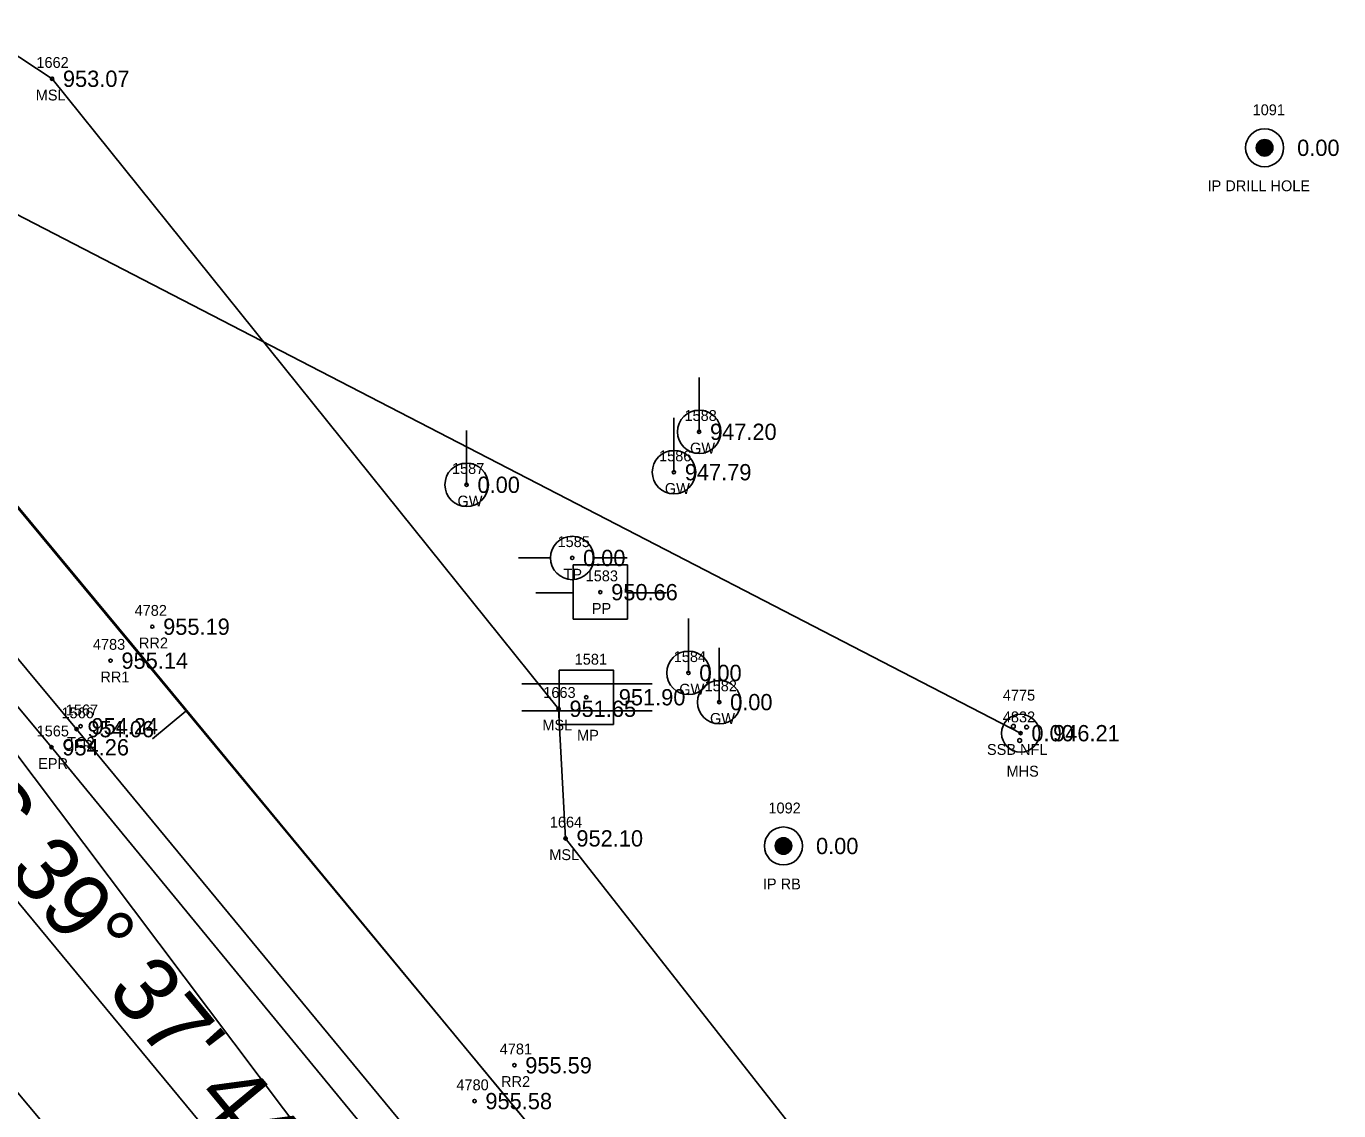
# Model space of a CAD drawing. Extents: x 1575382 to 1578175, y 1099175 to 1101955.
# Drawn here: x 1576480.6 to 1576601.4, y 1099501.7 to 1099601.6 of the extents above; entities that cross this region are included whole.
import ezdxf

# ---------------------------------------------------------------- set-up
doc = ezdxf.new("R2010")
doc.units = 0
for name, color, linetype in [('RD_EX_Conc', 7, 'Continuous'), ('RD_EX_Conc_txCode', 7, 'Continuous'), ('RD_EX_DR_Inlet', 7, 'Continuous'), ('RD_EX_DV_Prop_txCode', 7, 'Continuous'), ('RD_EX_DV_PropPin', 7, 'Continuous'), ('RD_EX_Misc', 7, 'Continuous'), ('RD_EX_Misc_txCode', 7, 'Continuous'), ('RD_EX_RailRoad', 7, 'Continuous'), ('RD_EX_RailRoad_txCode', 7, 'Continuous'), ('RD_EX_Road', 7, 'Continuous'), ('RD_EX_Road_txCode', 7, 'Continuous'), ('RD_EX_TX_Conc_ELEV', 7, 'Continuous'), ('RD_EX_TX_DV_Prop_ELEV', 7, 'Continuous'), ('RD_EX_TX_Misc_ELEV', 7, 'Continuous'), ('RD_EX_TX_RailRoad_ELEV', 7, 'Continuous'), ('RD_EX_TX_Road_ELEV', 7, 'Continuous'), ('RD_EX_TX_UT_ELEV', 7, 'Continuous'), ('RD_EX_UT', 7, 'Continuous'), ('RD_EX_UT_txCode', 7, 'Continuous'), ('RD_HC_Cl', 7, 'Continuous'), ('RD_HC_Data', 7, 'Continuous'), ('RD_HC_Data_Tic', 7, 'Continuous'), ('RD_HC_Survey_ELEV', 7, 'Continuous'), ('RD_SMD_Locator', 7, 'Continuous')]:
    doc.layers.add(name, color=color, linetype=linetype)

msp = doc.modelspace()

# ---------------------------------------------------------------- linework, layer by layer
at = {"layer": 'RD_EX_Conc'}
msp.add_lwpolyline([(1576448.28, 1099581.24), (1576485.22, 1099536.89), (1576516.55, 1099498.95), (1576548.71, 1099459.94), (1576580.64, 1099421.45)], dxfattribs=at)
at = {"layer": 'RD_EX_DR_Inlet'}
for centre, radius in [((1576572.13, 1099536.52), 1.75), ((1576571.47, 1099537.15), 0.175), ((1576572.69, 1099537.08), 0.175), ((1576572.05, 1099535.85), 0.175)]:
    msp.add_circle(centre, radius, dxfattribs=at)
at = {"layer": 'RD_EX_DV_PropPin'}
for p, q in [((1576593.87, 1099590.24), (1576593.87, 1099590.64)), ((1576593.9, 1099590.14), (1576593.9, 1099590.74)), ((1576593.94, 1099590.07), (1576593.94, 1099590.81)), ((1576593.97, 1099590.01), (1576593.97, 1099590.87)), ((1576594.01, 1099589.97), (1576594.01, 1099590.91)), ((1576594.04, 1099589.92), (1576594.04, 1099590.95)), ((1576594.08, 1099589.89), (1576594.08, 1099590.99)), ((1576594.11, 1099589.86), (1576594.11, 1099591.02)), ((1576594.15, 1099589.83), (1576594.15, 1099591.05)), ((1576594.18, 1099589.8), (1576594.18, 1099591.07)), ((1576594.22, 1099589.78), (1576594.22, 1099591.1)), ((1576594.25, 1099589.76), (1576594.25, 1099591.11)), ((1576594.29, 1099589.75), (1576594.29, 1099591.13)), ((1576594.32, 1099589.73), (1576594.32, 1099591.15)), ((1576594.36, 1099589.72), (1576594.36, 1099591.16)), ((1576594.39, 1099589.71), (1576594.39, 1099591.17)), ((1576594.43, 1099589.7), (1576594.43, 1099591.18)), ((1576594.46, 1099589.69), (1576594.46, 1099591.19)), ((1576594.5, 1099589.69), (1576594.5, 1099591.19)), ((1576594.53, 1099589.68), (1576594.53, 1099591.2)), ((1576594.57, 1099589.68), (1576594.57, 1099591.2)), ((1576594.6, 1099589.68), (1576594.6, 1099591.2)), ((1576594.64, 1099589.68), (1576594.64, 1099591.2)), ((1576594.67, 1099589.68), (1576594.67, 1099591.2)), ((1576594.71, 1099589.69), (1576594.71, 1099591.19)), ((1576594.74, 1099589.69), (1576594.74, 1099591.19)), ((1576594.78, 1099589.7), (1576594.78, 1099591.18)), ((1576594.81, 1099589.71), (1576594.81, 1099591.17)), ((1576594.85, 1099589.72), (1576594.85, 1099591.16)), ((1576594.88, 1099589.73), (1576594.88, 1099591.15)), ((1576594.92, 1099589.75), (1576594.92, 1099591.13)), ((1576594.95, 1099589.76), (1576594.95, 1099591.11)), ((1576594.99, 1099589.78), (1576594.99, 1099591.1)), ((1576595.02, 1099589.8), (1576595.02, 1099591.07)), ((1576595.06, 1099589.83), (1576595.06, 1099591.05)), ((1576595.09, 1099589.86), (1576595.09, 1099591.02)), ((1576595.13, 1099589.89), (1576595.13, 1099590.99)), ((1576595.16, 1099589.92), (1576595.16, 1099590.95)), ((1576595.2, 1099589.97), (1576595.2, 1099590.91)), ((1576595.23, 1099590.01), (1576595.23, 1099590.87)), ((1576595.27, 1099590.07), (1576595.27, 1099590.81)), ((1576595.3, 1099590.14), (1576595.3, 1099590.74)), ((1576595.34, 1099590.24), (1576595.34, 1099590.64)), ((1576549.57, 1099525.93), (1576549.57, 1099526.33)), ((1576549.6, 1099525.83), (1576549.6, 1099526.43)), ((1576549.64, 1099525.76), (1576549.64, 1099526.5)), ((1576549.67, 1099525.7), (1576549.67, 1099526.56)), ((1576549.71, 1099525.66), (1576549.71, 1099526.6)), ((1576549.74, 1099525.62), (1576549.74, 1099526.65)), ((1576549.78, 1099525.58), (1576549.78, 1099526.68)), ((1576549.81, 1099525.55), (1576549.81, 1099526.71)), ((1576549.85, 1099525.52), (1576549.85, 1099526.74)), ((1576549.88, 1099525.5), (1576549.88, 1099526.77)), ((1576549.92, 1099525.47), (1576549.92, 1099526.79)), ((1576549.95, 1099525.45), (1576549.95, 1099526.81)), ((1576549.99, 1099525.44), (1576549.99, 1099526.82)), ((1576550.02, 1099525.42), (1576550.02, 1099526.84)), ((1576550.06, 1099525.41), (1576550.06, 1099526.85)), ((1576550.09, 1099525.4), (1576550.09, 1099526.86)), ((1576550.13, 1099525.39), (1576550.13, 1099526.87)), ((1576550.16, 1099525.38), (1576550.16, 1099526.88)), ((1576550.2, 1099525.38), (1576550.2, 1099526.88)), ((1576550.23, 1099525.37), (1576550.23, 1099526.89)), ((1576550.27, 1099525.37), (1576550.27, 1099526.89)), ((1576550.3, 1099525.37), (1576550.3, 1099526.89)), ((1576550.34, 1099525.37), (1576550.34, 1099526.89)), ((1576550.37, 1099525.37), (1576550.37, 1099526.89)), ((1576550.41, 1099525.38), (1576550.41, 1099526.88)), ((1576550.44, 1099525.38), (1576550.44, 1099526.88)), ((1576550.48, 1099525.39), (1576550.48, 1099526.87)), ((1576550.51, 1099525.4), (1576550.51, 1099526.86)), ((1576550.55, 1099525.41), (1576550.55, 1099526.85)), ((1576550.58, 1099525.42), (1576550.58, 1099526.84)), ((1576550.62, 1099525.44), (1576550.62, 1099526.82)), ((1576550.65, 1099525.45), (1576550.65, 1099526.81)), ((1576550.69, 1099525.47), (1576550.69, 1099526.79)), ((1576550.72, 1099525.5), (1576550.72, 1099526.77)), ((1576550.76, 1099525.52), (1576550.76, 1099526.74)), ((1576550.79, 1099525.55), (1576550.79, 1099526.71)), ((1576550.83, 1099525.58), (1576550.83, 1099526.68)), ((1576550.86, 1099525.62), (1576550.86, 1099526.65)), ((1576550.9, 1099525.66), (1576550.9, 1099526.6)), ((1576550.93, 1099525.7), (1576550.93, 1099526.56)), ((1576550.97, 1099525.76), (1576550.97, 1099526.5)), ((1576551, 1099525.83), (1576551, 1099526.43)), ((1576551.04, 1099525.93), (1576551.04, 1099526.33))]:
    msp.add_line(p, q, dxfattribs=at)
for centre, radius in [((1576594.6, 1099590.44), 1.75), ((1576594.6, 1099590.44), 0.761), ((1576550.3, 1099526.13), 1.75), ((1576550.3, 1099526.13), 0.761)]:
    msp.add_circle(centre, radius, dxfattribs=at)
at = {"layer": 'RD_EX_Misc'}
msp.add_lwpolyline([(1576459.31, 1099612.41), (1576482.96, 1099596.8), (1576529.6, 1099538.77), (1576530.24, 1099526.83), (1576601.16, 1099436.41)], dxfattribs=at)
at = {"layer": 'RD_EX_RailRoad'}
msp.add_lwpolyline([(1576586.78, 1099428.1), (1576554.9, 1099466.71), (1576523.69, 1099504.28), (1576490.27, 1099544.77), (1576459.31, 1099582.09), (1576445.84, 1099598.34), (1576409.99, 1099641.44), (1576367.44, 1099692.66), (1576334.67, 1099732.08), (1576298.68, 1099775.46), (1576256.76, 1099825.95)], dxfattribs=at)
at = {"layer": 'RD_EX_Road'}
for points in [[(1576443.75, 1099596.96), (1576443.04, 1099588.29), (1576448.28, 1099581.24), (1576446.02, 1099579.49), (1576482.91, 1099535.22), (1576514.34, 1099496.99), (1576546.16, 1099458.39), (1576578.5, 1099419.58)], [(1576365.09, 1099547.1), (1576400.46, 1099578.87), (1576404.99, 1099582.28), (1576408.27, 1099583.27), (1576411.47, 1099582.29), (1576413.12, 1099580.85), (1576414.82, 1099582.11), (1576433.7, 1099559), (1576464.95, 1099521.11), (1576497.8, 1099481.91), (1576528.73, 1099444.46), (1576560.01, 1099406.61)]]:
    msp.add_lwpolyline(points, dxfattribs=at)
at = {"layer": 'RD_EX_UT'}
for p, q in [((1576542.54, 1099564.28), (1576542.54, 1099569.28)), ((1576540.22, 1099560.56), (1576540.22, 1099565.56)), ((1576521.13, 1099559.4), (1576521.13, 1099564.4)), ((1576525.92, 1099552.67), (1576528.85, 1099552.67)), ((1576535.93, 1099552.02), (1576530.93, 1099552.02)), ((1576530.93, 1099552.02), (1576530.93, 1099547.02)), ((1576532.85, 1099552.67), (1576535.92, 1099552.67)), ((1576535.93, 1099547.02), (1576535.93, 1099552.02)), ((1576527.5, 1099549.46), (1576530.97, 1099549.46)), ((1576535.86, 1099549.46), (1576539.5, 1099549.46)), ((1576530.93, 1099547.02), (1576535.93, 1099547.02)), ((1576541.55, 1099542.07), (1576541.55, 1099547.07)), ((1576544.39, 1099539.38), (1576544.39, 1099544.38)), ((1576526.21, 1099541.08), (1576538.21, 1099541.08)), ((1576526.21, 1099538.58), (1576538.21, 1099538.58))]:
    msp.add_line(p, q, dxfattribs=at)
for points in [[(1576131.49, 1099798.74), (1576305.27, 1099688.09), (1576417.78, 1099616.34), (1576572.13, 1099536.52)], [(1576589.46, 1099388.65), (1576430.6, 1099599.81), (1576417.78, 1099616.34)]]:
    msp.add_lwpolyline(points, dxfattribs=at)
msp.add_lwpolyline([(1576529.64, 1099542.33), (1576534.64, 1099542.33), (1576534.64, 1099537.33), (1576529.64, 1099537.33)], close=True, dxfattribs=at)
for centre in [(1576542.54, 1099564.28), (1576521.13, 1099559.4), (1576540.22, 1099560.56), (1576530.85, 1099552.66), (1576541.55, 1099542.07), (1576544.39, 1099539.38)]:
    msp.add_circle(centre, 2, dxfattribs=at)
at = {"layer": 'RD_HC_Cl'}
for p, q in [((1576594.9, 1099418.51), (1576256.8, 1099825.98)), ((1576414.59, 1099599.72), (1576569.26, 1099412.94))]:
    msp.add_line(p, q, dxfattribs=at)
at = {"layer": 'RD_HC_Data_Tic'}
msp.add_line((1576495.28, 1099538.56), (1576492.21, 1099536.01), dxfattribs=at)
at = {"layer": 'RD_SMD_Locator'}
for centre, radius in [((1576482.96, 1099596.8), 0.15), ((1576594.6, 1099590.44), 0.15), ((1576542.54, 1099564.28), 0.15), ((1576540.22, 1099560.56), 0.15), ((1576521.13, 1099559.4), 0.15), ((1576530.85, 1099552.66), 0.15), ((1576533.44, 1099549.51), 0.15), ((1576492.19, 1099546.33), 0.15), ((1576488.35, 1099543.2), 0.15), ((1576541.55, 1099542.07), 0.15), ((1576532.14, 1099539.83), 0.15), ((1576529.6, 1099538.77), 0.15), ((1576544.39, 1099539.38), 0.15), ((1576485.59, 1099537.16), 0.15), ((1576485.22, 1099536.89), 0.15), ((1576572.13, 1099536.52), 0.15), ((1576572.13, 1099536.52), 0.001), ((1576482.91, 1099535.22), 0.15), ((1576530.24, 1099526.83), 0.15), ((1576550.3, 1099526.13), 0.15), ((1576525.53, 1099505.93), 0.15), ((1576521.86, 1099502.63), 0.15)]:
    msp.add_circle(centre, radius, dxfattribs=at)

# ---------------------------------------------------------------- texts
at = {"layer": 'RD_EX_Conc_txCode'}
for s, p in [('1566', (1576483.83, 1099537.89)), ('1567', (1576484.22, 1099538.16)), ('TC2', (1576484.35, 1099535.16)), ('CFR', (1576483.99, 1099534.89))]:
    msp.add_text(s, height=1, dxfattribs=at).set_placement(p)
at = {"layer": 'RD_EX_DV_Prop_txCode'}
for s, p in [('1091', (1576593.5, 1099593.44)), ('IP DRILL HOLE', (1576589.35, 1099586.44)), ('1092', (1576548.92, 1099529.13)), ('IP RB', (1576548.41, 1099522.13))]:
    msp.add_text(s, height=1, dxfattribs=at).set_placement(p)
at = {"layer": 'RD_EX_Misc_txCode'}
for s, p in [('1662', (1576481.52, 1099597.8)), ('MSL', (1576481.46, 1099594.8)), ('1663', (1576528.19, 1099539.77)), ('MSL', (1576528.1, 1099536.77)), ('1664', (1576528.79, 1099527.83)), ('MSL', (1576528.74, 1099524.83))]:
    msp.add_text(s, height=1, dxfattribs=at).set_placement(p)
at = {"layer": 'RD_EX_RailRoad_txCode'}
for s, p in [('4782', (1576490.56, 1099547.33)), ('4783', (1576486.72, 1099544.2)), ('RR2', (1576490.96, 1099544.33)), ('RR1', (1576487.41, 1099541.2)), ('4781', (1576524.18, 1099506.93)), ('4780', (1576520.19, 1099503.63)), ('RR2', (1576524.3, 1099503.93))]:
    msp.add_text(s, height=1, dxfattribs=at).set_placement(p)
at = {"layer": 'RD_EX_Road_txCode'}
for s, p in [('1565', (1576481.54, 1099536.22)), ('EPR', (1576481.68, 1099533.22))]:
    msp.add_text(s, height=1, dxfattribs=at).set_placement(p)
at = {"layer": 'RD_EX_TX_Conc_ELEV'}
for s, p in [('954.06', (1576486.22, 1099536.14)), ('954.24', (1576486.59, 1099536.41))]:
    msp.add_text(s, height=1.5, dxfattribs=at).set_placement(p)
at = {"layer": 'RD_EX_TX_DV_Prop_ELEV'}
for p in [(1576597.6, 1099589.69), (1576553.3, 1099525.38)]:
    msp.add_text('0.00', height=1.5, dxfattribs=at).set_placement(p)
at = {"layer": 'RD_EX_TX_Misc_ELEV'}
for s, p in [('953.07', (1576483.96, 1099596.05)), ('951.65', (1576530.6, 1099538.02)), ('952.10', (1576531.24, 1099526.08))]:
    msp.add_text(s, height=1.5, dxfattribs=at).set_placement(p)
at = {"layer": 'RD_EX_TX_RailRoad_ELEV'}
for s, p in [('955.19', (1576493.19, 1099545.58)), ('955.14', (1576489.35, 1099542.45)), ('955.59', (1576526.53, 1099505.18)), ('955.58', (1576522.86, 1099501.88))]:
    msp.add_text(s, height=1.5, dxfattribs=at).set_placement(p)
at = {"layer": 'RD_EX_TX_Road_ELEV'}
msp.add_text('954.26', height=1.5, dxfattribs=at).set_placement((1576483.91, 1099534.47))
at = {"layer": 'RD_EX_TX_UT_ELEV'}
for s, p in [('947.20', (1576543.54, 1099563.53)), ('0.00', (1576522.13, 1099558.65)), ('947.79', (1576541.22, 1099559.81)), ('0.00', (1576531.85, 1099551.91)), ('0.00', (1576542.55, 1099541.32)), ('951.90', (1576535.14, 1099539.08)), ('0.00', (1576545.39, 1099538.63)), ('0.00', (1576573.13, 1099535.77)), ('946.21', (1576575.13, 1099535.77))]:
    msp.add_text(s, height=1.5, dxfattribs=at).set_placement(p)
at = {"layer": 'RD_EX_UT_txCode'}
for s, p in [('1588', (1576541.19, 1099565.28)), ('1586', (1576538.85, 1099561.56)), ('GW', (1576541.7, 1099562.28)), ('1587', (1576519.78, 1099560.4)), ('GW', (1576539.38, 1099558.56)), ('GW', (1576520.29, 1099557.4)), ('1585', (1576529.5, 1099553.66)), ('TP', (1576530.05, 1099550.66)), ('1583', (1576532.09, 1099550.51)), ('PP', (1576532.66, 1099547.51)), ('1581', (1576531.08, 1099542.83)), ('1584', (1576540.2, 1099543.07)), ('GW', (1576540.71, 1099540.07)), ('1582', (1576543.04, 1099540.38)), ('4775', (1576570.5, 1099539.52)), ('4832', (1576570.5, 1099537.52)), ('GW', (1576543.54, 1099537.38)), ('MP', (1576531.3, 1099535.83)), ('SSB NFL', (1576569.04, 1099534.52)), ('MHS', (1576570.84, 1099532.52))]:
    msp.add_text(s, height=1, dxfattribs=at).set_placement(p)
at = {"layer": 'RD_HC_Data'}
msp.add_text('S 39%%d 37\' 44" E', height=6, rotation=309.6288, dxfattribs=at).set_placement((1576473.91, 1099529.66))
at = {"layer": 'RD_HC_Survey_ELEV'}
msp.add_text('950.66', height=1.5, dxfattribs=at).set_placement((1576534.44, 1099548.76))

doc.saveas('drawing.dxf')
